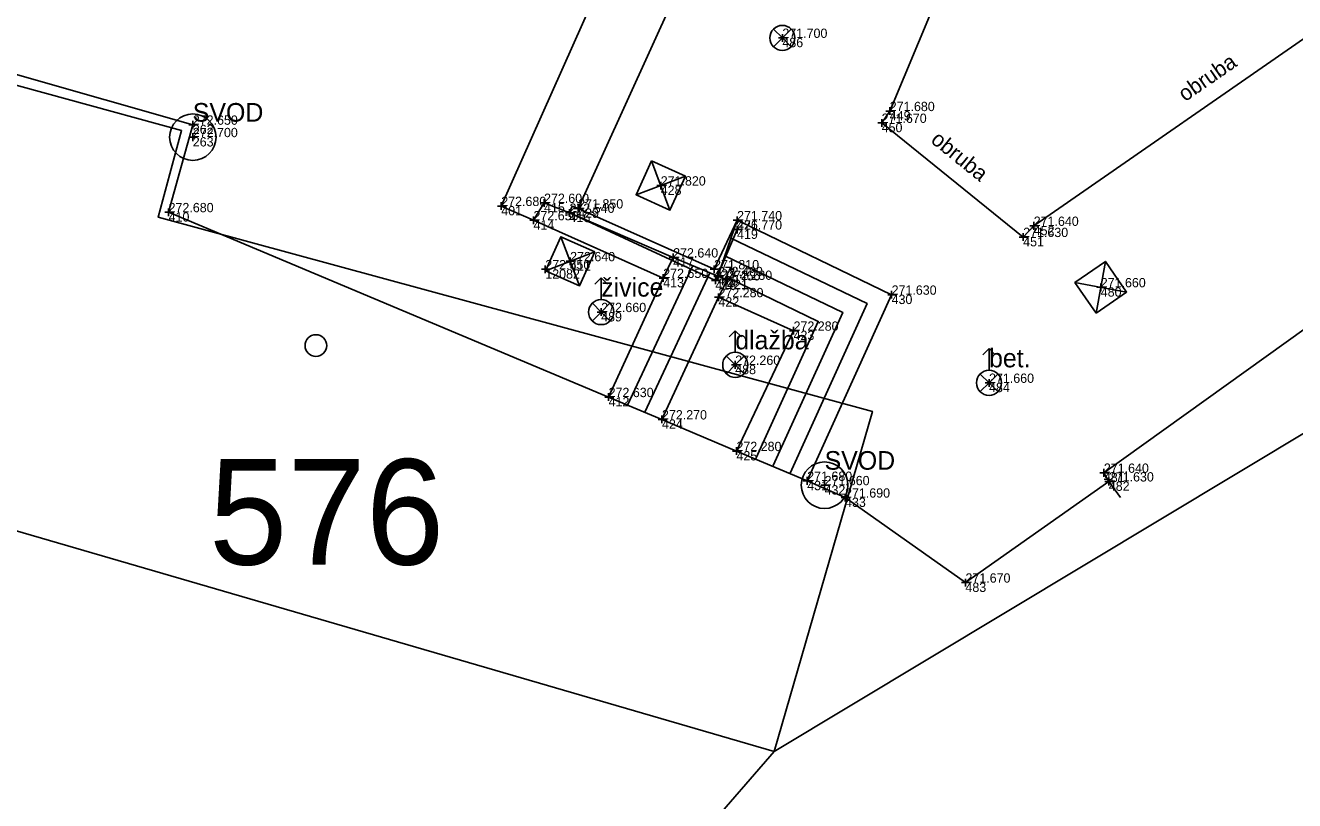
# Model space of a CAD drawing. Extents: x -776606 to -776076, y -974328 to -973875.
# Drawn here: x -776349.29 to -776328.84, y -974220.11 to -974207.62 of the extents above; entities that cross this region are included whole.
import ezdxf

# ---------------------------------------------------------------- set-up
doc = ezdxf.new("R2010")
doc.units = 0
for name, color, linetype in [('Body polohopisu', 7, 'Continuous'), ('Budovy', 7, 'Continuous'), ('Doplňkové značky', 7, 'Continuous'), ('Doplňující texty', 7, 'Continuous'), ('Hranice parcel', 7, 'Continuous'), ('Nezařazené objekty', 7, 'Continuous'), ('Parcelní čísla', 7, 'Continuous'), ('Ploty_opěrné zdi', 7, 'Continuous'), ('Rozhraní ploch', 7, 'Continuous'), ('Vstup na pozemek', 7, 'Continuous'), ('Výškopis', 7, 'Continuous'), ('Výšky bodů', 7, 'Continuous'), ('Značky budov', 7, 'Continuous'), ('Značky IS', 7, 'Continuous'), ('Čísla bodů', 7, 'Continuous')]:
    doc.layers.add(name, color=color, linetype=linetype)

msp = doc.modelspace()

# ---------------------------------------------------------------- linework, layer by layer
at = {"layer": 'Body polohopisu'}
for p, q in [((-776337.09, -974207.82), (-776337.152, -974207.82)), ((-776337.09, -974207.82), (-776337.09, -974207.758)), ((-776337.09, -974207.82), (-776337.027, -974207.82)), ((-776337.09, -974207.82), (-776337.09, -974207.883)), ((-776335.49, -974209.19), (-776335.49, -974209.128)), ((-776335.36, -974209), (-776335.422, -974209)), ((-776335.36, -974209), (-776335.36, -974208.938)), ((-776335.36, -974209), (-776335.297, -974209)), ((-776335.36, -974209), (-776335.36, -974209.062)), ((-776346.59, -974209.22), (-776346.652, -974209.22)), ((-776346.59, -974209.22), (-776346.59, -974209.157)), ((-776346.59, -974209.22), (-776346.527, -974209.22)), ((-776346.59, -974209.22), (-776346.59, -974209.282)), ((-776335.49, -974209.19), (-776335.552, -974209.19)), ((-776335.49, -974209.19), (-776335.427, -974209.19)), ((-776335.49, -974209.19), (-776335.49, -974209.253)), ((-776346.59, -974209.42), (-776346.652, -974209.42)), ((-776346.59, -974209.42), (-776346.59, -974209.358)), ((-776346.59, -974209.42), (-776346.527, -974209.42)), ((-776346.59, -974209.42), (-776346.59, -974209.483)), ((-776339.05, -974210.2), (-776339.05, -974210.138)), ((-776339.05, -974210.2), (-776339.113, -974210.2)), ((-776339.05, -974210.2), (-776338.988, -974210.2)), ((-776339.05, -974210.2), (-776339.05, -974210.263)), ((-776341.62, -974210.53), (-776341.682, -974210.53)), ((-776341.62, -974210.53), (-776341.62, -974210.468)), ((-776341.62, -974210.53), (-776341.557, -974210.53)), ((-776341.62, -974210.53), (-776341.62, -974210.593)), ((-776340.93, -974210.48), (-776340.993, -974210.48)), ((-776340.93, -974210.48), (-776340.93, -974210.417)), ((-776340.93, -974210.48), (-776340.868, -974210.48)), ((-776340.93, -974210.48), (-776340.93, -974210.542)), ((-776340.38, -974210.57), (-776340.38, -974210.508)), ((-776346.98, -974210.63), (-776347.042, -974210.63)), ((-776346.98, -974210.63), (-776346.98, -974210.568)), ((-776346.98, -974210.63), (-776346.917, -974210.63)), ((-776346.98, -974210.63), (-776346.98, -974210.693)), ((-776341.1, -974210.76), (-776341.162, -974210.76)), ((-776341.1, -974210.76), (-776341.1, -974210.698)), ((-776341.1, -974210.76), (-776341.037, -974210.76)), ((-776341.1, -974210.76), (-776341.1, -974210.823)), ((-776340.52, -974210.64), (-776340.583, -974210.64)), ((-776340.52, -974210.64), (-776340.52, -974210.578)), ((-776340.52, -974210.64), (-776340.458, -974210.64)), ((-776340.52, -974210.64), (-776340.52, -974210.703)), ((-776340.38, -974210.57), (-776340.443, -974210.57)), ((-776340.38, -974210.57), (-776340.318, -974210.57)), ((-776340.38, -974210.57), (-776340.38, -974210.633)), ((-776337.82, -974210.76), (-776337.883, -974210.76)), ((-776337.82, -974210.76), (-776337.82, -974210.698)), ((-776337.82, -974210.76), (-776337.758, -974210.76)), ((-776337.82, -974210.76), (-776337.82, -974210.823)), ((-776337.82, -974210.91), (-776337.883, -974210.91)), ((-776337.82, -974210.91), (-776337.82, -974210.848)), ((-776337.82, -974210.91), (-776337.758, -974210.91)), ((-776337.82, -974210.91), (-776337.82, -974210.973)), ((-776333.21, -974211.03), (-776333.21, -974210.968)), ((-776333.04, -974210.85), (-776333.103, -974210.85)), ((-776333.04, -974210.85), (-776333.04, -974210.787)), ((-776333.04, -974210.85), (-776332.978, -974210.85)), ((-776333.04, -974210.85), (-776333.04, -974210.912)), ((-776333.21, -974211.03), (-776333.272, -974211.03)), ((-776333.21, -974211.03), (-776333.147, -974211.03)), ((-776333.21, -974211.03), (-776333.21, -974211.093)), ((-776340.51, -974211.42), (-776340.51, -974211.358)), ((-776338.85, -974211.36), (-776338.912, -974211.36)), ((-776338.85, -974211.36), (-776338.85, -974211.297)), ((-776338.85, -974211.36), (-776338.787, -974211.36)), ((-776338.85, -974211.36), (-776338.85, -974211.422)), ((-776340.91, -974211.55), (-776340.973, -974211.55)), ((-776340.91, -974211.55), (-776340.91, -974211.488)), ((-776340.91, -974211.55), (-776340.848, -974211.55)), ((-776340.91, -974211.55), (-776340.91, -974211.613)), ((-776340.51, -974211.42), (-776340.573, -974211.42)), ((-776340.51, -974211.42), (-776340.448, -974211.42)), ((-776340.51, -974211.42), (-776340.51, -974211.483)), ((-776338.19, -974211.55), (-776338.253, -974211.55)), ((-776338.19, -974211.55), (-776338.19, -974211.488)), ((-776338.19, -974211.55), (-776338.128, -974211.55)), ((-776338.19, -974211.55), (-776338.19, -974211.613)), ((-776339.01, -974211.69), (-776339.073, -974211.69)), ((-776339.01, -974211.69), (-776339.01, -974211.628)), ((-776339.01, -974211.69), (-776338.948, -974211.69)), ((-776339.01, -974211.69), (-776339.01, -974211.753)), ((-776338.17, -974211.73), (-776338.233, -974211.73)), ((-776338.13, -974211.66), (-776338.193, -974211.66)), ((-776338.17, -974211.73), (-776338.17, -974211.667)), ((-776338.17, -974211.73), (-776338.108, -974211.73)), ((-776338.17, -974211.73), (-776338.17, -974211.792)), ((-776338.13, -974211.66), (-776338.13, -974211.598)), ((-776338.13, -974211.66), (-776338.068, -974211.66)), ((-776338.13, -974211.66), (-776338.13, -974211.723)), ((-776337.98, -974211.72), (-776338.042, -974211.72)), ((-776337.98, -974211.72), (-776337.98, -974211.657)), ((-776337.98, -974211.72), (-776337.917, -974211.72)), ((-776337.98, -974211.72), (-776337.98, -974211.782)), ((-776331.96, -974211.84), (-776331.96, -974211.777)), ((-776338.12, -974212), (-776338.12, -974211.938)), ((-776335.33, -974211.96), (-776335.392, -974211.96)), ((-776335.33, -974211.96), (-776335.33, -974211.897)), ((-776335.33, -974211.96), (-776335.267, -974211.96)), ((-776335.33, -974211.96), (-776335.33, -974212.022)), ((-776331.96, -974211.84), (-776332.022, -974211.84)), ((-776331.96, -974211.84), (-776331.897, -974211.84)), ((-776331.96, -974211.84), (-776331.96, -974211.902)), ((-776340.01, -974212.24), (-776340.01, -974212.177)), ((-776338.12, -974212), (-776338.182, -974212)), ((-776338.12, -974212), (-776338.057, -974212)), ((-776338.12, -974212), (-776338.12, -974212.062)), ((-776340.01, -974212.24), (-776340.073, -974212.24)), ((-776340.01, -974212.24), (-776339.948, -974212.24)), ((-776340.01, -974212.24), (-776340.01, -974212.302)), ((-776336.91, -974212.54), (-776336.973, -974212.54)), ((-776336.91, -974212.54), (-776336.91, -974212.478)), ((-776336.91, -974212.54), (-776336.848, -974212.54)), ((-776336.91, -974212.54), (-776336.91, -974212.603)), ((-776337.85, -974213.09), (-776337.912, -974213.09)), ((-776337.85, -974213.09), (-776337.85, -974213.027)), ((-776337.85, -974213.09), (-776337.787, -974213.09)), ((-776337.85, -974213.09), (-776337.85, -974213.152)), ((-776333.76, -974213.38), (-776333.823, -974213.38)), ((-776333.76, -974213.38), (-776333.76, -974213.318)), ((-776333.76, -974213.38), (-776333.698, -974213.38)), ((-776333.76, -974213.38), (-776333.76, -974213.443)), ((-776339.89, -974213.61), (-776339.953, -974213.61)), ((-776339.89, -974213.61), (-776339.89, -974213.547)), ((-776339.89, -974213.61), (-776339.828, -974213.61)), ((-776339.89, -974213.61), (-776339.89, -974213.672)), ((-776339.03, -974213.97), (-776339.093, -974213.97)), ((-776339.03, -974213.97), (-776339.03, -974213.907)), ((-776339.03, -974213.97), (-776338.968, -974213.97)), ((-776339.03, -974213.97), (-776339.03, -974214.032)), ((-776337.83, -974214.48), (-776337.83, -974214.417)), ((-776337.83, -974214.48), (-776337.892, -974214.48)), ((-776337.83, -974214.48), (-776337.767, -974214.48)), ((-776337.83, -974214.48), (-776337.83, -974214.542)), ((-776331.91, -974214.83), (-776331.973, -974214.83)), ((-776331.91, -974214.83), (-776331.91, -974214.768)), ((-776331.91, -974214.83), (-776331.848, -974214.83)), ((-776331.91, -974214.83), (-776331.91, -974214.893)), ((-776336.69, -974214.96), (-776336.753, -974214.96)), ((-776336.69, -974214.96), (-776336.69, -974214.897)), ((-776336.69, -974214.96), (-776336.628, -974214.96)), ((-776336.69, -974214.96), (-776336.69, -974215.022)), ((-776336.41, -974215.03), (-776336.473, -974215.03)), ((-776336.41, -974215.03), (-776336.41, -974214.968)), ((-776336.41, -974215.03), (-776336.348, -974215.03)), ((-776336.41, -974215.03), (-776336.41, -974215.093)), ((-776331.83, -974214.97), (-776331.892, -974214.97)), ((-776331.83, -974214.97), (-776331.83, -974214.907)), ((-776331.83, -974214.97), (-776331.767, -974214.97)), ((-776331.83, -974214.97), (-776331.83, -974215.032)), ((-776336.08, -974215.23), (-776336.142, -974215.23)), ((-776336.08, -974215.23), (-776336.08, -974215.167)), ((-776336.08, -974215.23), (-776336.017, -974215.23)), ((-776336.08, -974215.23), (-776336.08, -974215.292)), ((-776334.14, -974216.6), (-776334.203, -974216.6)), ((-776334.14, -974216.6), (-776334.14, -974216.537)), ((-776334.14, -974216.6), (-776334.078, -974216.6)), ((-776334.14, -974216.6), (-776334.14, -974216.662))]:
    msp.add_line(p, q, dxfattribs=at)
at = {"layer": 'Budovy'}
msp.add_lwpolyline([(-776350.83, -974208.01), (-776346.59, -974209.22), (-776346.98, -974210.63), (-776339.89, -974213.61), (-776339.03, -974213.97), (-776337.83, -974214.48), (-776336.69, -974214.96), (-776336.08, -974215.23), (-776334.14, -974216.6)], dxfattribs=at)
at = {"layer": 'Doplňkové značky'}
for p, q in [((-776337.09, -974207.82), (-776337.232, -974207.677)), ((-776337.09, -974207.82), (-776336.948, -974207.677)), ((-776337.09, -974207.82), (-776337.232, -974207.962)), ((-776337.09, -974207.82), (-776337.09, -974207.82)), ((-776337.09, -974207.82), (-776336.948, -974207.962)), ((-776340.01, -974211.689), (-776340.11, -974211.79)), ((-776340.01, -974212.038), (-776340.01, -974211.689)), ((-776340.01, -974211.689), (-776339.91, -974211.79)), ((-776340.01, -974212.24), (-776340.152, -974212.098)), ((-776340.01, -974212.24), (-776339.868, -974212.098)), ((-776340.01, -974212.24), (-776340.152, -974212.382)), ((-776340.01, -974212.24), (-776340.01, -974212.24)), ((-776340.01, -974212.24), (-776339.868, -974212.382)), ((-776337.85, -974212.54), (-776337.949, -974212.64)), ((-776337.85, -974212.888), (-776337.85, -974212.54)), ((-776337.85, -974212.54), (-776337.75, -974212.64)), ((-776337.85, -974213.09), (-776337.992, -974212.948)), ((-776337.85, -974213.09), (-776337.708, -974212.948)), ((-776333.76, -974212.829), (-776333.86, -974212.93)), ((-776333.76, -974213.178), (-776333.76, -974212.829)), ((-776333.76, -974212.829), (-776333.66, -974212.93)), ((-776337.85, -974213.09), (-776337.992, -974213.232)), ((-776337.85, -974213.09), (-776337.85, -974213.09)), ((-776337.85, -974213.09), (-776337.708, -974213.232)), ((-776333.76, -974213.38), (-776333.902, -974213.238)), ((-776333.76, -974213.38), (-776333.902, -974213.522)), ((-776333.76, -974213.38), (-776333.618, -974213.238)), ((-776333.76, -974213.38), (-776333.76, -974213.38)), ((-776333.76, -974213.38), (-776333.618, -974213.522))]:
    msp.add_line(p, q, dxfattribs=at)
for centre, radius in [((-776337.09, -974207.82), 0.202), ((-776346.59, -974209.42), 0.375), ((-776340.01, -974212.24), 0.202), ((-776337.85, -974213.09), 0.202), ((-776333.76, -974213.38), 0.202), ((-776336.41, -974215.03), 0.375)]:
    msp.add_circle(centre, radius, dxfattribs=at)
at = {"layer": 'Hranice parcel'}
for p, q in [((-776352.27, -974214.94), (-776337.22, -974219.32)), ((-776337.22, -974219.32), (-776340.63, -974223.24))]:
    msp.add_line(p, q, dxfattribs=at)
for points in [[(-776274.82, -974171.4), (-776320.22, -974209.13), (-776324.76, -974211.83), (-776337.22, -974219.32)], [(-776350.46, -974208.3), (-776346.77, -974209.31), (-776347.15, -974210.71), (-776335.64, -974213.84), (-776337.22, -974219.32)]]:
    msp.add_lwpolyline(points, dxfattribs=at)
at = {"layer": 'Nezařazené objekty'}
msp.add_lwpolyline([(-776333.51, -974204.57), (-776335.36, -974209), (-776335.49, -974209.19), (-776333.21, -974211.03), (-776333.04, -974210.85), (-776328.22, -974207.51), (-776328.32, -974207.35), (-776333.51, -974204.57)], dxfattribs=at)
at = {"layer": 'Ploty_opěrné zdi'}
msp.add_line((-776340.38, -974210.57), (-776338.32, -974206.03), dxfattribs=at)
for points in [[(-776337.67, -974202.074), (-776339.98, -974206.84), (-776341.62, -974210.53), (-776341.1, -974210.76), (-776340.93, -974210.48)], [(-776321.923, -974208.856), (-776322.46, -974208.14), (-776327, -974211.31), (-776331.91, -974214.83), (-776331.83, -974214.97), (-776331.644, -974215.229)], [(-776340.93, -974210.48), (-776340.52, -974210.64), (-776340.478, -974210.532), (-776340.38, -974210.57)], [(-776340.52, -974210.64), (-776338.17, -974211.73), (-776337.82, -974210.91)], [(-776337.82, -974210.76), (-776338.19, -974211.55), (-776340.38, -974210.57)]]:
    msp.add_lwpolyline(points, dxfattribs=at)
at = {"layer": 'Rozhraní ploch'}
for p, q in [((-776338.535, -974211.491), (-776339.584, -974213.738)), ((-776338.258, -974211.607), (-776339.307, -974213.854))]:
    msp.add_line(p, q, dxfattribs=at)
for points in [[(-776339.01, -974211.69), (-776341.1, -974210.76)], [(-776338.13, -974211.66), (-776337.82, -974210.76), (-776335.33, -974211.96), (-776336.69, -974214.96)], [(-776337.918, -974211.046), (-776335.724, -974212.103), (-776336.963, -974214.836)], [(-776339.89, -974213.61), (-776339.01, -974211.69), (-776338.85, -974211.36), (-776338.13, -974211.66), (-776337.98, -974211.72), (-776338.12, -974212), (-776339.03, -974213.97)], [(-776338.017, -974211.331), (-776336.118, -974212.246), (-776337.236, -974214.712)], [(-776337.98, -974211.72), (-776337.965, -974211.689), (-776336.513, -974212.389), (-776337.51, -974214.588)], [(-776338.12, -974212), (-776336.91, -974212.54), (-776337.83, -974214.48)]]:
    msp.add_lwpolyline(points, dxfattribs=at)
at = {"layer": 'Vstup na pozemek'}
msp.add_lwpolyline([(-776331.83, -974214.97), (-776334.14, -974216.6)], dxfattribs=at)
at = {"layer": 'Výškopis'}
msp.add_lwpolyline([(-776340.52, -974210.64), (-776338.85, -974211.36)], dxfattribs=at)
at = {"layer": 'Značky budov'}
msp.add_circle((-776344.607, -974212.779), 0.175, dxfattribs=at)
at = {"layer": 'Značky IS'}
for p, q in [((-776338.901, -974210.597), (-776339.199, -974209.803)), ((-776338.653, -974210.051), (-776339.447, -974210.349)), ((-776340.358, -974211.816), (-776340.662, -974211.024)), ((-776340.906, -974211.572), (-776340.114, -974211.268)), ((-776331.884, -974211.423), (-776332.036, -974212.257)), ((-776332.377, -974211.764), (-776331.543, -974211.916))]:
    msp.add_line(p, q, dxfattribs=at)
for points in [[(-776339.199, -974209.803), (-776339.447, -974210.349), (-776338.901, -974210.597), (-776338.653, -974210.051)], [(-776340.114, -974211.268), (-776340.662, -974211.024), (-776340.906, -974211.572), (-776340.358, -974211.816)], [(-776332.036, -974212.257), (-776331.543, -974211.916), (-776331.884, -974211.423), (-776332.377, -974211.764)]]:
    msp.add_lwpolyline(points, close=True, dxfattribs=at)

# ---------------------------------------------------------------- texts
at = {"layer": 'Doplňující texty'}
for rotation, p in [(34.7199, (-776330.601, -974208.856)), (321.0959, (-776334.715, -974209.494))]:
    msp.add_text('obruba', height=0.25, rotation=rotation, dxfattribs=at).set_placement(p)
for s, p in [('SVOD', (-776346.59, -974209.17)), ('živice', (-776340.01, -974211.99)), ('dlažba', (-776337.85, -974212.84)), ('bet.', (-776333.76, -974213.13)), ('SVOD', (-776336.41, -974214.78))]:
    msp.add_text(s, height=0.3, dxfattribs=at).set_placement(p)
at = {"layer": 'Parcelní čísla'}
msp.add_text('576', height=1.7, dxfattribs=at).set_placement((-776346.33, -974216.31))
at = {"layer": 'Výšky bodů'}
for s, p in [('271.700', (-776337.09, -974207.82)), ('271.680', (-776335.36, -974209)), ('272.650', (-776346.59, -974209.22)), ('271.670', (-776335.49, -974209.19)), ('272.700', (-776346.59, -974209.42)), ('271.820', (-776339.05, -974210.2)), ('272.600', (-776340.93, -974210.48)), ('272.680', (-776346.98, -974210.63)), ('272.680', (-776341.62, -974210.53)), ('272.540', (-776340.52, -974210.64)), ('271.850', (-776340.38, -974210.57)), ('272.650', (-776341.1, -974210.76)), ('271.740', (-776337.82, -974210.76)), ('271.770', (-776337.82, -974210.91)), ('271.640', (-776333.04, -974210.85)), ('271.630', (-776333.21, -974211.03)), ('272.640', (-776340.51, -974211.42)), ('272.640', (-776338.85, -974211.36)), ('272.650', (-776340.91, -974211.55)), ('272.650', (-776339.01, -974211.69)), ('271.810', (-776338.19, -974211.55)), ('272.460', (-776338.17, -974211.73)), ('272.460', (-776338.13, -974211.66)), ('272.280', (-776337.98, -974211.72)), ('271.660', (-776331.96, -974211.84)), ('272.280', (-776338.12, -974212)), ('271.630', (-776335.33, -974211.96)), ('272.660', (-776340.01, -974212.24)), ('272.280', (-776336.91, -974212.54)), ('272.260', (-776337.85, -974213.09)), ('271.660', (-776333.76, -974213.38)), ('272.630', (-776339.89, -974213.61)), ('272.270', (-776339.03, -974213.97)), ('272.280', (-776337.83, -974214.48)), ('271.680', (-776336.69, -974214.96)), ('271.640', (-776331.91, -974214.83)), ('271.630', (-776331.83, -974214.97)), ('271.660', (-776336.41, -974215.03)), ('271.690', (-776336.08, -974215.23)), ('271.670', (-776334.14, -974216.6))]:
    msp.add_text(s, height=0.15, dxfattribs=at).set_placement(p)
at = {"layer": 'Čísla bodů'}
for s, p in [('486', (-776337.09, -974207.97)), ('449', (-776335.36, -974209.15)), ('262', (-776346.59, -974209.37)), ('450', (-776335.49, -974209.34)), ('263', (-776346.59, -974209.57)), ('428', (-776339.05, -974210.35)), ('401', (-776341.62, -974210.68)), ('415', (-776340.93, -974210.63)), ('410', (-776346.98, -974210.78)), ('414', (-776341.1, -974210.91)), ('416', (-776340.52, -974210.79)), ('429', (-776340.38, -974210.72)), ('426', (-776337.82, -974210.91)), ('419', (-776337.82, -974211.06)), ('452', (-776333.04, -974211)), ('451', (-776333.21, -974211.18)), ('417', (-776338.85, -974211.51)), ('12082', (-776340.91, -974211.7)), ('411', (-776340.51, -974211.57)), ('427', (-776338.19, -974211.7)), ('413', (-776339.01, -974211.84)), ('418', (-776338.17, -974211.88)), ('420', (-776338.13, -974211.81)), ('421', (-776337.98, -974211.87)), ('430', (-776335.33, -974212.11)), ('480', (-776331.96, -974211.99)), ('422', (-776338.12, -974212.15)), ('489', (-776340.01, -974212.39)), ('423', (-776336.91, -974212.69)), ('488', (-776337.85, -974213.24)), ('484', (-776333.76, -974213.53)), ('412', (-776339.89, -974213.76)), ('424', (-776339.03, -974214.12)), ('425', (-776337.83, -974214.63)), ('481', (-776331.91, -974214.98)), ('431', (-776336.69, -974215.11)), ('432', (-776336.41, -974215.18)), ('482', (-776331.83, -974215.12)), ('433', (-776336.08, -974215.38)), ('483', (-776334.14, -974216.75))]:
    msp.add_text(s, height=0.15, dxfattribs=at).set_placement(p)

doc.saveas('drawing.dxf')
